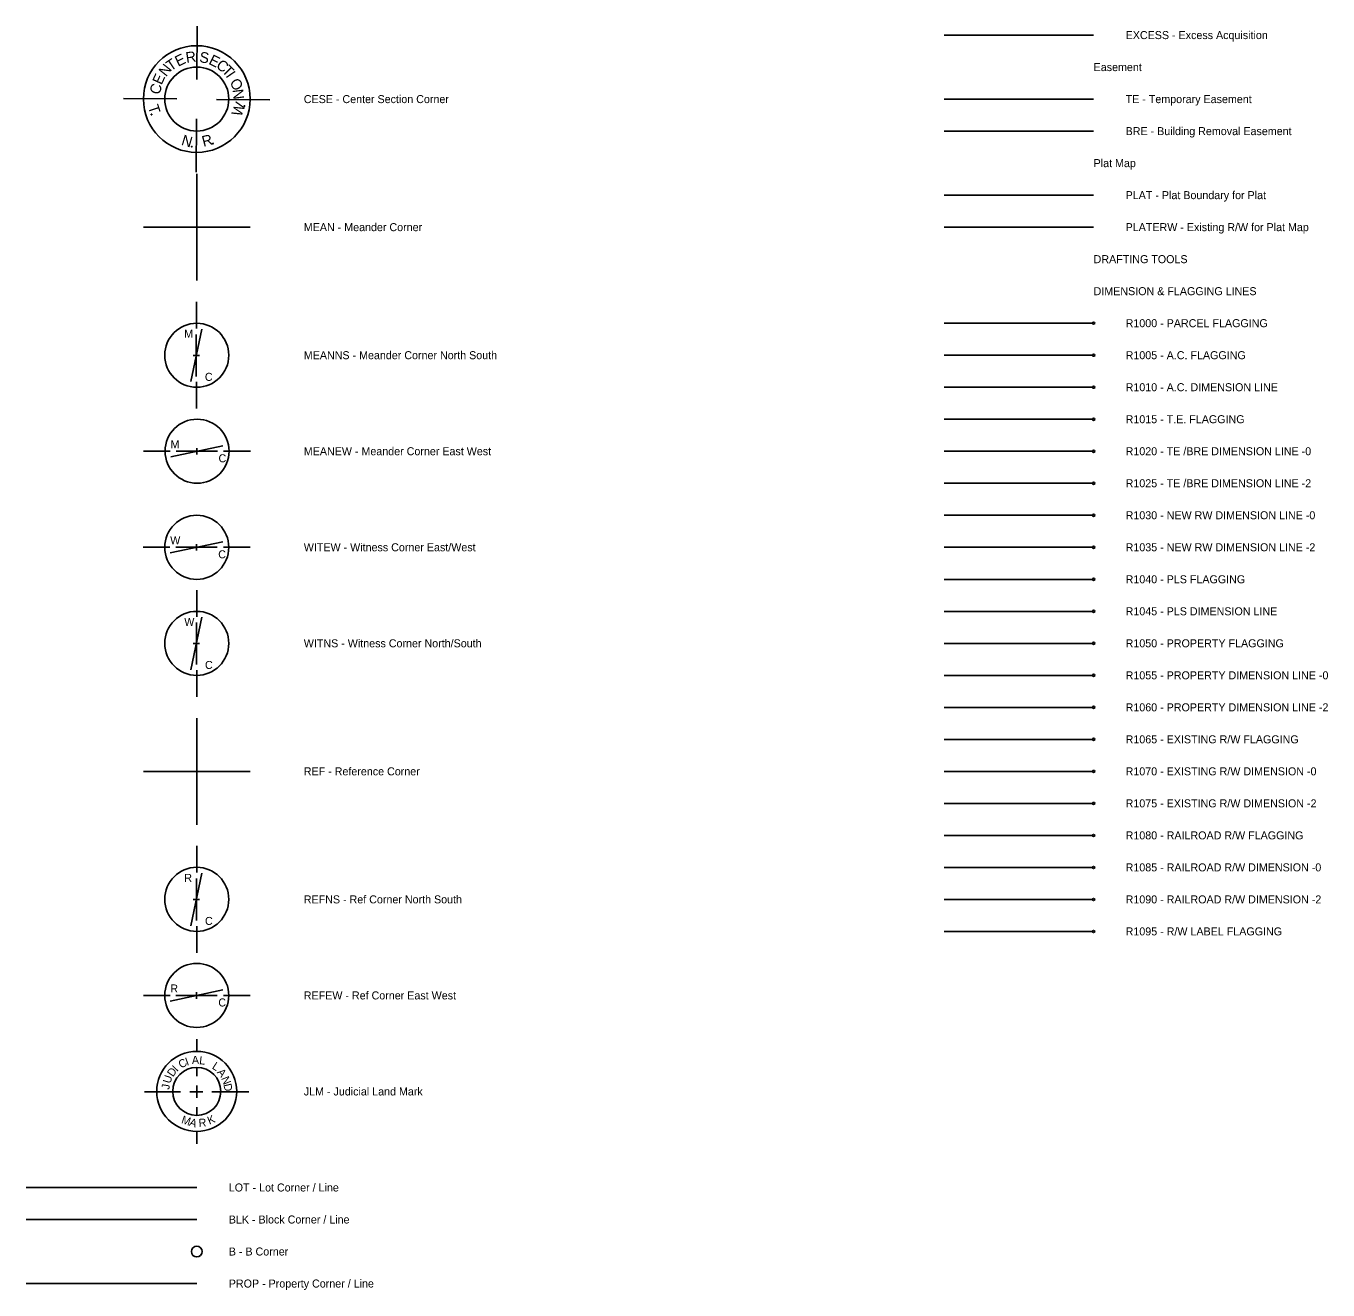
# Model space of a CAD drawing. Extents: x 2147716 to 2176321, y 2125040 to 2131750.
# Drawn here: x 2167430 to 2168650, y 2127709 to 2128893 of the extents above; entities that cross this region are included whole.
import ezdxf

# ---------------------------------------------------------------- set-up
doc = ezdxf.new("R2010")
doc.units = 0
for name, color, linetype in [('ACC CTRL DIM', 7, 'Continuous'), ('ACQ CHN RW', 7, 'Continuous'), ('B PT', 7, 'Continuous'), ('Default', 7, 'Continuous'), ('ESMT DIM', 7, 'Continuous'), ('ESMT FLAG', 7, 'Continuous'), ('ESMT TEMP', 7, 'Continuous'), ('GPK DEF', 7, 'Continuous'), ('PAR FLAG', 7, 'Continuous'), ('PLAT BDRY', 7, 'Continuous'), ('PLS INP', 7, 'Continuous'), ('PLS MLS INP DIM', 7, 'Continuous'), ('PROP INP', 7, 'Continuous'), ('RW INP', 7, 'Continuous'), ('RW INP DIM', 7, 'Continuous'), ('RW INP FLAG', 7, 'Continuous'), ('RW TXT DIM', 7, 'Continuous'), ('SUBD INP', 7, 'Continuous')]:
    doc.layers.add(name, color=color, linetype=linetype)

msp = doc.modelspace()

# ---------------------------------------------------------------- linework, layer by layer
at = {"layer": 'ACC CTRL DIM'}
msp.add_line((2168430.5, 2128554.8), (2168290.5, 2128554.8), dxfattribs=at)
msp.add_circle((2168430.5, 2128554.8), 1, dxfattribs=at)
at = {"layer": 'ACQ CHN RW'}
msp.add_line((2168430.5, 2128884.8), (2168290.5, 2128884.8), dxfattribs=at)
at = {"layer": 'B PT'}
msp.add_circle((2167590, 2127744.8), 5, dxfattribs=at)
at = {"layer": 'ESMT DIM'}
for p, q in [((2168430.5, 2128494.8), (2168290.5, 2128494.8)), ((2168430.5, 2128464.8), (2168290.5, 2128464.8))]:
    msp.add_line(p, q, dxfattribs=at)
for centre in [(2168430.5, 2128494.8), (2168430.5, 2128464.8)]:
    msp.add_circle(centre, 1, dxfattribs=at)
at = {"layer": 'ESMT FLAG'}
msp.add_line((2168430.5, 2128524.8), (2168290.5, 2128524.8), dxfattribs=at)
msp.add_circle((2168430.5, 2128524.8), 1, dxfattribs=at)
at = {"layer": 'ESMT TEMP'}
for p, q in [((2168430.5, 2128824.8), (2168290.5, 2128824.8)), ((2168430.5, 2128794.8), (2168290.5, 2128794.8))]:
    msp.add_line(p, q, dxfattribs=at)
at = {"layer": 'GPK DEF'}
for p, q in [((2167590, 2128754.8), (2167590, 2128654.8)), ((2167640, 2128704.8), (2167540, 2128704.8)), ((2167590, 2128244.8), (2167590, 2128144.8)), ((2167640, 2128194.8), (2167540, 2128194.8))]:
    msp.add_line(p, q, dxfattribs=at)
at = {"layer": 'PAR FLAG'}
for p, q in [((2168430.5, 2128614.8), (2168290.5, 2128614.8)), ((2168430.5, 2128584.8), (2168290.5, 2128584.8)), ((2168430.5, 2128314.8), (2168290.5, 2128314.8))]:
    msp.add_line(p, q, dxfattribs=at)
for centre in [(2168430.5, 2128614.8), (2168430.5, 2128584.8), (2168430.5, 2128314.8)]:
    msp.add_circle(centre, 1, dxfattribs=at)
at = {"layer": 'PLAT BDRY'}
msp.add_line((2168430.5, 2128734.8), (2168290.5, 2128734.8), dxfattribs=at)
at = {"layer": 'PLS INP'}
for p, q in [((2167590.1, 2128843.3), (2167590.5, 2128893.3)), ((2167521.4, 2128825.4), (2167571.4, 2128825)), ((2167608.4, 2128824.6), (2167658.4, 2128824.2)), ((2167589.3, 2128756.3), (2167589.7, 2128806.3)), ((2167589.9, 2128609.8), (2167589.9, 2128634.8)), ((2167584.3, 2128560.1), (2167594.7, 2128609.3)), ((2167589.5, 2128604.4), (2167589.5, 2128565)), ((2167589.5, 2128584.7), (2167586.5, 2128584.7)), ((2167589.5, 2128584.9), (2167589.5, 2128584.9)), ((2167589.5, 2128584.7), (2167592.5, 2128584.7)), ((2167589.9, 2128559.8), (2167589.9, 2128534.8)), ((2167565.7, 2128489.7), (2167614.3, 2128499.9)), ((2167590, 2128494.8), (2167590, 2128497.8)), ((2167540.2, 2128494.8), (2167565.2, 2128494.8)), ((2167570.7, 2128494.8), (2167609.3, 2128494.8)), ((2167589.8, 2128494.8), (2167589.8, 2128494.8)), ((2167590, 2128491.8), (2167590, 2128494.8)), ((2167615.2, 2128494.8), (2167640.2, 2128494.8)), ((2167539.9, 2128404.8), (2167564.9, 2128404.8)), ((2167565, 2128399.6), (2167614.4, 2128410)), ((2167570.4, 2128404.8), (2167609, 2128404.8)), ((2167589.5, 2128404.8), (2167589.5, 2128404.8)), ((2167589.7, 2128404.8), (2167589.7, 2128407.8)), ((2167589.7, 2128404.8), (2167589.7, 2128401.8)), ((2167614.9, 2128404.8), (2167639.9, 2128404.8)), ((2168430.5, 2128374.8), (2168290.5, 2128374.8)), ((2167590, 2128339.8), (2167590, 2128364.8)), ((2167584.4, 2128290.1), (2167594.8, 2128339.3)), ((2167589.6, 2128334.4), (2167589.6, 2128295)), ((2167589.6, 2128314.7), (2167586.6, 2128314.7)), ((2167589.6, 2128314.9), (2167589.6, 2128314.9)), ((2167589.6, 2128314.7), (2167592.6, 2128314.7)), ((2167590, 2128289.8), (2167590, 2128264.8)), ((2167590, 2128099.9), (2167590, 2128124.9)), ((2167584.4, 2128050.2), (2167594.8, 2128099.4)), ((2167589.6, 2128094.5), (2167589.6, 2128055.1)), ((2167589.6, 2128074.8), (2167586.6, 2128074.8)), ((2167589.6, 2128074.9), (2167589.6, 2128074.9)), ((2167589.6, 2128074.8), (2167592.6, 2128074.8)), ((2167590, 2128049.9), (2167590, 2128024.9)), ((2167540, 2127984.8), (2167565, 2127984.8)), ((2167565.2, 2127979.5), (2167614.4, 2127990.1)), ((2167570.5, 2127984.8), (2167609.1, 2127984.8)), ((2167589.6, 2127984.8), (2167589.6, 2127984.8)), ((2167589.8, 2127984.8), (2167589.8, 2127987.8)), ((2167589.8, 2127981.8), (2167589.8, 2127984.8)), ((2167615, 2127984.8), (2167640, 2127984.8)), ((2167590, 2127932.4), (2167590, 2127943.9)), ((2167590, 2127909.3), (2167590, 2127917.4)), ((2167590, 2127889), (2167590, 2127900.5)), ((2167574.6, 2127894.6), (2167541, 2127894.6)), ((2167595.6, 2127894.6), (2167583.5, 2127894.6)), ((2167590, 2127894.9), (2167590, 2127894.6)), ((2167604.1, 2127894.6), (2167638.9, 2127894.6)), ((2167590, 2127880.1), (2167590, 2127872.4)), ((2167590, 2127857.4), (2167590, 2127845.9))]:
    msp.add_line(p, q, dxfattribs=at)
for centre, radius in [((2167590, 2128824.9), 50), ((2167590, 2128824.9), 30), ((2167634.7, 2128818.4), 0.3), ((2167547.6, 2128810.4), 0.3), ((2167585.3, 2128780.3), 0.3), ((2167605.3, 2128783.3), 0.3), ((2167590, 2128584.8), 30), ((2167590.3, 2128494.9), 30), ((2167590, 2128404.8), 30), ((2168430.5, 2128374.8), 1), ((2167590, 2128314.8), 30), ((2167590, 2128074.9), 30), ((2167590, 2127984.8), 30), ((2167590, 2127894.9), 37.5), ((2167590, 2127894.9), 22.5)]:
    msp.add_circle(centre, radius, dxfattribs=at)
at = {"layer": 'PLS MLS INP DIM'}
msp.add_line((2168430.5, 2128344.8), (2168290.5, 2128344.8), dxfattribs=at)
msp.add_circle((2168430.5, 2128344.8), 1, dxfattribs=at)
at = {"layer": 'PROP INP'}
for p, q in [((2168430.5, 2128284.8), (2168290.5, 2128284.8)), ((2168430.5, 2128254.8), (2168290.5, 2128254.8)), ((2167590, 2127714.8), (2167430, 2127714.8))]:
    msp.add_line(p, q, dxfattribs=at)
for centre in [(2168430.5, 2128284.8), (2168430.5, 2128254.8)]:
    msp.add_circle(centre, 1, dxfattribs=at)
at = {"layer": 'RW INP'}
msp.add_line((2168430.5, 2128704.8), (2168290.5, 2128704.8), dxfattribs=at)
at = {"layer": 'RW INP DIM'}
for p, q in [((2168430.5, 2128194.8), (2168290.5, 2128194.8)), ((2168430.5, 2128164.8), (2168290.5, 2128164.8)), ((2168430.5, 2128104.8), (2168290.5, 2128104.8)), ((2168430.5, 2128074.8), (2168290.5, 2128074.8))]:
    msp.add_line(p, q, dxfattribs=at)
for centre in [(2168430.5, 2128194.8), (2168430.5, 2128164.8), (2168430.5, 2128104.8), (2168430.5, 2128074.8)]:
    msp.add_circle(centre, 1, dxfattribs=at)
at = {"layer": 'RW INP FLAG'}
for p, q in [((2168430.5, 2128224.8), (2168290.5, 2128224.8)), ((2168430.5, 2128134.8), (2168290.5, 2128134.8)), ((2168430.5, 2128044.8), (2168290.5, 2128044.8))]:
    msp.add_line(p, q, dxfattribs=at)
for centre in [(2168430.5, 2128224.8), (2168430.5, 2128134.8), (2168430.5, 2128044.8)]:
    msp.add_circle(centre, 1, dxfattribs=at)
at = {"layer": 'RW TXT DIM'}
for p, q in [((2168430.5, 2128434.8), (2168290.5, 2128434.8)), ((2168430.5, 2128404.8), (2168290.5, 2128404.8))]:
    msp.add_line(p, q, dxfattribs=at)
for centre in [(2168430.5, 2128434.8), (2168430.5, 2128404.8)]:
    msp.add_circle(centre, 1, dxfattribs=at)
at = {"layer": 'SUBD INP'}
for p, q in [((2167590, 2127804.8), (2167430, 2127804.8)), ((2167590, 2127774.8), (2167430, 2127774.8))]:
    msp.add_line(p, q, dxfattribs=at)

# ---------------------------------------------------------------- texts
at = {"layer": 'Default'}
for s, p in [('EXCESS - Excess Acquisition', (2168460.5, 2128881.1)), ('Easement', (2168430.5, 2128851.1)), ('CESE - Center Section Corner', (2167690.3, 2128821.1)), ('TE - Temporary Easement', (2168460.5, 2128821.1)), ('BRE - Building Removal Easement', (2168460.5, 2128791.1)), ('Plat Map', (2168430.5, 2128761.1)), ('PLAT - Plat Boundary for Plat', (2168460.5, 2128731.1)), ('MEAN - Meander Corner', (2167690.3, 2128701.1)), ('PLATERW - Existing R/W for Plat Map', (2168460.5, 2128701.1)), ('DRAFTING TOOLS', (2168430.5, 2128671.1)), ('DIMENSION & FLAGGING LINES', (2168430.5, 2128641.1)), ('R1000 - PARCEL FLAGGING', (2168460.5, 2128611.1)), ('MEANNS - Meander Corner North South', (2167690.3, 2128581.1)), ('R1005 - A.C. FLAGGING', (2168460.5, 2128581.1)), ('R1010 - A.C. DIMENSION LINE', (2168460.5, 2128551.1)), ('R1015 - T.E. FLAGGING', (2168460.5, 2128521.1)), ('MEANEW - Meander Corner East West', (2167690.3, 2128491.1)), ('R1020 - TE /BRE DIMENSION LINE -0', (2168460.5, 2128491.1)), ('R1025 - TE /BRE DIMENSION LINE -2', (2168460.5, 2128461.1)), ('R1030 - NEW RW DIMENSION LINE -0', (2168460.5, 2128431.1)), ('WITEW - Witness Corner East/West', (2167690.3, 2128401.1)), ('R1035 - NEW RW DIMENSION LINE -2', (2168460.5, 2128401.1)), ('R1040 - PLS FLAGGING', (2168460.5, 2128371.1)), ('R1045 - PLS DIMENSION LINE', (2168460.5, 2128341.1)), ('WITNS - Witness Corner North/South', (2167690.3, 2128311.1)), ('R1050 - PROPERTY FLAGGING', (2168460.5, 2128311.1)), ('R1055 - PROPERTY DIMENSION LINE -0', (2168460.5, 2128281.1)), ('R1060 - PROPERTY DIMENSION LINE -2', (2168460.5, 2128251.1)), ('R1065 - EXISTING R/W FLAGGING', (2168460.5, 2128221.1)), ('REF - Reference Corner', (2167690.3, 2128191.1)), ('R1070 - EXISTING R/W DIMENSION -0', (2168460.5, 2128191.1)), ('R1075 - EXISTING R/W DIMENSION -2', (2168460.5, 2128161.1)), ('R1080 - RAILROAD R/W FLAGGING', (2168460.5, 2128131.1)), ('R1085 - RAILROAD R/W DIMENSION -0', (2168460.5, 2128101.1)), ('REFNS - Ref Corner North South', (2167690.3, 2128071.1)), ('R1090 - RAILROAD R/W DIMENSION -2', (2168460.5, 2128071.1)), ('R1095 - R/W LABEL FLAGGING', (2168460.5, 2128041.1)), ('REFEW - Ref Corner East West', (2167690.3, 2127981.1)), ('JLM - Judicial Land Mark', (2167690.3, 2127891.1)), ('LOT - Lot Corner / Line', (2167620, 2127801.1)), ('BLK - Block Corner / Line', (2167620, 2127771.1)), ('B - B Corner', (2167620, 2127741.1)), ('PROP - Property Corner / Line', (2167620, 2127711.1))]:
    msp.add_text(s, height=7.5, dxfattribs=at).set_placement(p)
at = {"layer": 'PLS INP'}
for s, height, rotation, p in [('T', 10, 34.3025, (2167565.6, 2128850.7)), ('E', 10, 25.6946, (2167572.5, 2128855.1)), ('R', 10, 8.6953, (2167580.4, 2128858.7)), ('S', 10, 351.8558, (2167592, 2128859.5)), ('E', 10, 333.3184, (2167600.4, 2128858.2)), ('N', 10, 51.6315, (2167561.3, 2128845.2)), ('C', 10, 326.9714, (2167607.4, 2128854.4)), ('T', 10, 314.5065, (2167612.9, 2128850.8)), ('I', 10, 304.4985, (2167616.7, 2128846.7)), ('C', 10, 75.2692, (2167555.2, 2128828.5)), ('E', 10, 65.544, (2167557, 2128837.6)), ('O', 10, 302.9719, (2167620.3, 2128840.3)), ('N', 10, 277.2716, (2167623.4, 2128833.6)), ('T', 10, 288.1938, (2167544.1, 2128817.8)), ('W', 10, 69.5065, (2167631.6, 2128807.7)), ('N', 10, 343.2124, (2167574.9, 2128782.2)), ('R', 10, 14.7616, (2167596.3, 2128780.1)), ('C', 7.5, 28.7641, (2167575.3, 2127916.2)), ('I', 7.5, 19.9667, (2167580.8, 2127918.9)), ('A', 7.5, 2.372, (2167585.5, 2127920.5)), ('L', 7.5, 353.5747, (2167592, 2127920.5)), ('D', 7.5, 55.1561, (2167567.7, 2127908)), ('I', 7.5, 46.3587, (2167571.6, 2127912.9)), ('L', 7.5, 327.1827, (2167603.7, 2127916.7)), ('A', 7.5, 309.588, (2167608.6, 2127912.6)), ('J', 7.5, 81.5481, (2167564.2, 2127896.3)), ('U', 7.5, 72.7507, (2167565.2, 2127901.8)), ('N', 7.5, 291.9933, (2167612.8, 2127907.2)), ('D', 7.5, 283.196, (2167614.9, 2127901.3)), ('M', 7.5, 342.1117, (2167575, 2127865.3)), ('A', 7.5, 341.8523, (2167582.4, 2127863)), ('R', 7.5, 4.0842, (2167592, 2127861.6)), ('K', 7.5, 22.4608, (2167601.8, 2127863.7))]:
    msp.add_text(s, height=height, rotation=rotation, dxfattribs=at).set_placement(p)
for s, p in [('M', (2167578.2, 2128601.2)), ('C', (2167597.6, 2128560.8)), ('M', (2167565.4, 2128497.6)), ('C', (2167610.4, 2128484.5)), ('W', (2167565.1, 2128407.6)), ('C', (2167610.1, 2128394.5)), ('W', (2167578.3, 2128331.2)), ('C', (2167597.7, 2128290.8)), ('R', (2167578.3, 2128091.3)), ('C', (2167597.7, 2128050.9)), ('R', (2167565.2, 2127987.6)), ('C', (2167610.2, 2127974.5))]:
    msp.add_text(s, height=7.5, dxfattribs=at).set_placement(p)

doc.saveas('drawing.dxf')
